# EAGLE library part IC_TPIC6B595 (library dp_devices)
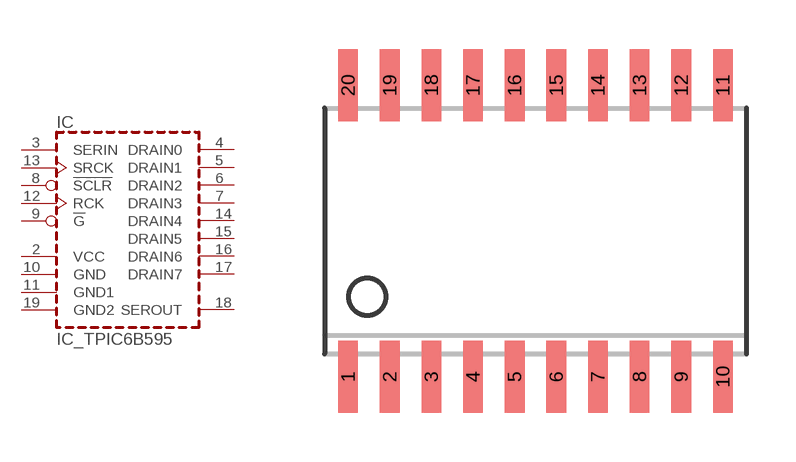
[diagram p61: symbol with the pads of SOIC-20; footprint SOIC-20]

Designator prefix IC

## IC_TPIC6B595DW  [SOIC-20]
2  VCC  pwr
3  SERIN  in
4  DRAIN0  out
5  DRAIN1  out
6  DRAIN2  out
7  DRAIN3  out
8  !SCLR  in
9  !G  in
10  GND  pwr
11  GND1  pwr
12  RCK  in
13  SRCK  in
14  DRAIN4  out
15  DRAIN5  out
16  DRAIN6  out
17  DRAIN7  out
18  SEROUT  out
19  GND2  pwr

## Footprint SOIC-20 (pad centres in mm)
smd 0.6 x 2.2: 1 -5.715,-4.445; 2 -4.445,-4.445; 3 -3.175,-4.445; 4 -1.905,-4.445; 5 -0.635,-4.445; 6 0.635,-4.445; 7 1.905,-4.445; 8 3.175,-4.445; 9 4.445,-4.445; 10 5.715,-4.445; 11 5.715,4.445; 12 4.445,4.445; 13 3.175,4.445; 14 1.905,4.445; 15 0.635,4.445; 16 -0.635,4.445; 17 -1.905,4.445; 18 -3.175,4.445; 19 -4.445,4.445; 20 -5.715,4.445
